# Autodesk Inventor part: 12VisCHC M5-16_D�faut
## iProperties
Created: 2011-01
Part Number: 12VisCHC M5-16_D�faut
Document SubType Name: Modeling
Designer: eric
Density: 1 g/cm^3
Mass: 0.560016 g
Surface Area: 5.22208 cm^2
Volume: 0.560016 cm^3
Author: eric
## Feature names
1. Base1
